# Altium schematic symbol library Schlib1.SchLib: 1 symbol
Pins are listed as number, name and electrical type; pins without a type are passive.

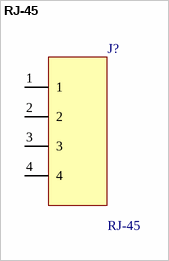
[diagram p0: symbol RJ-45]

## RJ-45
designator J?
footprint rj_45
pins: 1, 2, 3, 4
